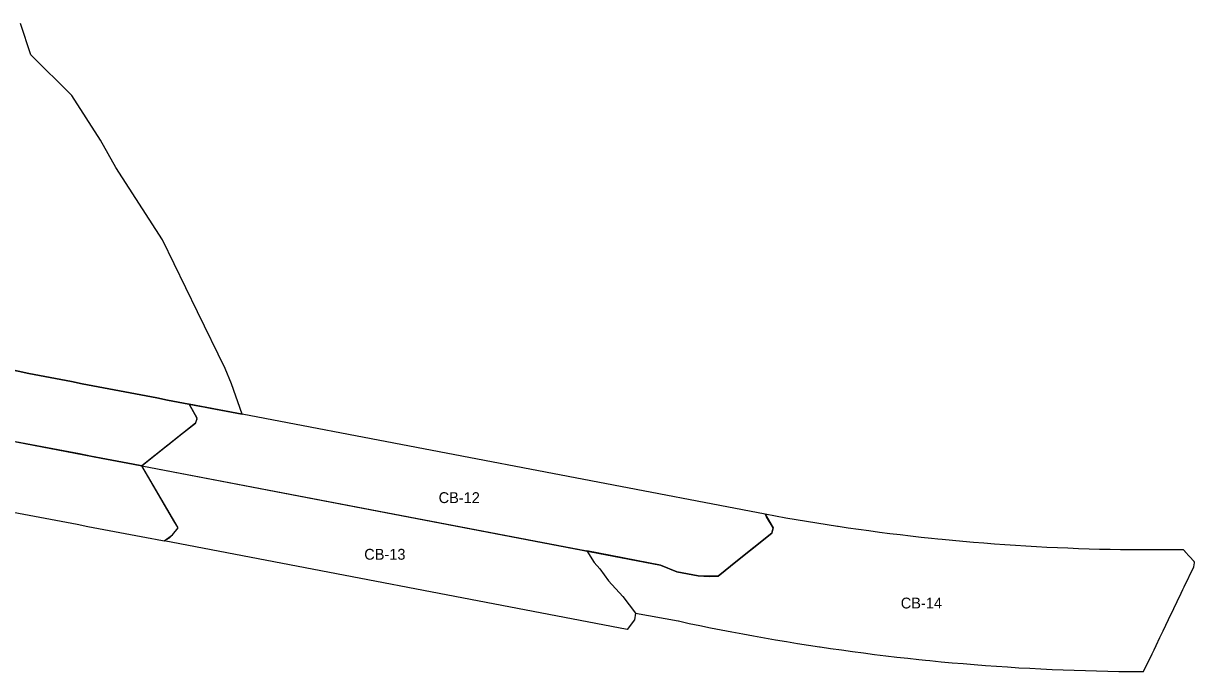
# Model space of a CAD drawing. Extents: x 2451 to 3960, y 2751 to 3762.
# Drawn here: x 3422 to 3960, y 2999 to 3297 of the extents above; entities that cross this region are included whole.
import ezdxf

# ---------------------------------------------------------------- set-up
doc = ezdxf.new("R2010")
doc.units = 0
doc.layers.add('SURVEY - DRAINAGE - Area Shapes', color=7, linetype='Continuous')
doc.layers.add('SURVEY - DRAINAGE - Area Shapes Text', color=7, linetype='Continuous')

msp = doc.modelspace()

# ---------------------------------------------------------------- linework, layer by layer
at = {"layer": 'SURVEY - DRAINAGE - Area Shapes'}
for p, q in [((3501.35, 3115.29), (3501.35, 3115.29)), ((3489.06, 3104.18), (3492.83, 3107.2)), ((3475.92, 3093.68), (3475.92, 3093.68)), ((3490.7, 3068.43), (3490.7, 3068.43)), ((3960.21, 3049.17), (3960.21, 3049.18)), ((3960.21, 3049.16), (3960.21, 3049.17))]:
    msp.add_line(p, q, dxfattribs=at)
for points in [[(3504.34, 3120.85), (3504.34, 3120.82), (3504.34, 3120.82), (3507.42, 3120.31), (3512.32, 3119.36), (3522.13, 3117.42), (3517.23, 3131.44), (3514.23, 3138.52), (3501.62, 3164.62), (3485.54, 3197.81), (3463.94, 3231), (3456.92, 3243.56), (3443.77, 3264.19), (3424.85, 3282.93), (3420.16, 3297.38)], [(3497.58, 3122.12), (3492.67, 3123.06), (3487.76, 3124), (3482.85, 3124.94), (3477.94, 3125.88), (3473.02, 3126.82), (3468.11, 3127.76), (3463.2, 3128.7), (3458.29, 3129.64), (3453.38, 3130.58), (3448.47, 3131.52), (3443.56, 3132.45), (3438.65, 3133.39), (3433.74, 3134.33), (3428.83, 3135.27), (3423.92, 3136.21), (3414.13, 3138.29)], [(3414.13, 3138.29), (3423.92, 3136.21)], [(3423.92, 3136.21), (3428.83, 3135.27), (3433.74, 3134.33), (3438.65, 3133.39), (3443.56, 3132.45), (3448.47, 3131.52), (3453.38, 3130.58), (3458.29, 3129.64), (3463.2, 3128.7), (3468.11, 3127.76), (3473.02, 3126.82), (3477.94, 3125.88), (3482.85, 3124.94), (3487.76, 3124), (3492.67, 3123.06), (3497.58, 3122.12), (3502.49, 3121.18), (3504.34, 3120.82), (3504.34, 3120.84), (3504.34, 3120.84), (3504.34, 3120.85)], [(3501.35, 3115.29), (3501.25, 3115.79), (3501.25, 3115.81), (3499.66, 3118.6), (3498.32, 3120.96), (3498.22, 3121.14), (3497.67, 3122.1), (3497.58, 3122.12)], [(3358.97, 3116.06), (3457.19, 3097.27), (3462.1, 3096.33), (3467.01, 3095.39), (3471.92, 3094.45), (3475.92, 3093.68), (3477.04, 3094.57), (3480.71, 3097.51)], [(3492.83, 3107.2), (3495.07, 3108.98), (3500.58, 3113.4), (3501.35, 3115.28), (3501.35, 3115.29)], [(3475.92, 3093.68), (3471.92, 3094.45), (3467.01, 3095.39), (3462.1, 3096.33), (3457.19, 3097.27), (3452.28, 3098.21), (3447.37, 3099.15), (3442.46, 3100.09), (3437.54, 3101.02), (3432.63, 3101.96), (3427.72, 3102.9), (3422.81, 3103.84), (3417.9, 3104.78)], [(3480.71, 3097.51), (3483.05, 3099.37), (3484.75, 3100.74), (3488.26, 3103.54), (3488.79, 3103.97), (3489.06, 3104.18)], [(3490.7, 3068.43), (3475.92, 3093.68)], [(3416.8, 3072.41), (3421.71, 3071.48)], [(3421.71, 3071.48), (3426.62, 3070.53), (3431.53, 3069.6), (3436.44, 3068.66), (3441.35, 3067.72), (3446.26, 3066.78), (3451.17, 3065.84), (3456.08, 3064.9), (3461, 3063.96), (3465.91, 3063.02), (3470.82, 3062.08), (3475.73, 3061.14), (3480.64, 3060.2)], [(3960.21, 3049.18), (3960.17, 3049.27), (3960.01, 3049.65), (3960, 3049.67), (3957.84, 3052.03), (3955.96, 3054.1), (3955.84, 3054.22), (3955.22, 3054.91), (3955.06, 3055.08), (3950.37, 3055.02), (3945.53, 3054.98), (3940.69, 3054.97), (3935.85, 3054.98), (3931.01, 3055.01), (3926.18, 3055.07), (3921.34, 3055.15), (3916.5, 3055.26), (3911.66, 3055.39), (3906.82, 3055.55), (3901.98, 3055.73), (3897.15, 3055.93), (3892.31, 3056.16), (3887.48, 3056.41), (3882.65, 3056.68), (3877.82, 3056.98), (3872.99, 3057.31), (3868.16, 3057.66), (3863.34, 3058.03), (3858.51, 3058.43), (3853.69, 3058.85), (3848.87, 3059.29), (3844.05, 3059.76), (3842.11, 3059.96), (3839.24, 3060.25), (3834.43, 3060.77), (3829.62, 3061.31), (3824.81, 3061.88), (3820.01, 3062.47), (3815.21, 3063.08), (3810.41, 3063.72), (3805.61, 3064.38), (3800.82, 3065.06), (3796.28, 3065.74), (3796.03, 3065.77), (3791.25, 3066.51), (3786.47, 3067.26), (3781.69, 3068.05), (3776.92, 3068.85), (3772.15, 3069.68), (3767.39, 3070.53), (3762.63, 3071.41), (3766.41, 3065.14), (3765.78, 3062.69), (3749.92, 3050.08), (3741.01, 3042.95), (3731.88, 3042.99), (3722.06, 3044.88), (3714.55, 3048.02), (3680.67, 3054.5)], [(3480.64, 3060.2), (3482.24, 3059.89), (3486.24, 3059.15), (3488.7, 3060.62), (3490.11, 3061.86), (3492.75, 3065.09), (3490.7, 3068.43)], [(3680.67, 3054.5), (3684.09, 3049.26), (3686.7, 3046.33), (3690.58, 3040.72), (3697.17, 3033.49), (3703.11, 3025.89), (3722.72, 3022.29), (3722.83, 3022.27), (3727.69, 3021.07), (3732.6, 3020.13), (3737.51, 3019.19), (3742.42, 3018.25), (3747.33, 3017.31), (3752.35, 3016.36), (3757.39, 3015.43), (3762.43, 3014.53), (3767.47, 3013.65), (3772.52, 3012.8), (3777.57, 3011.98), (3782.63, 3011.17), (3787.69, 3010.4), (3787.95, 3010.36), (3792.75, 3009.65), (3797.82, 3008.92), (3802.89, 3008.22), (3807.97, 3007.55), (3813.05, 3006.9), (3818.13, 3006.28), (3823.22, 3005.68), (3828.3, 3005.11), (3833.39, 3004.56), (3836.43, 3004.25), (3838.49, 3004.04), (3843.58, 3003.54), (3848.68, 3003.07), (3853.78, 3002.63), (3858.89, 3002.21), (3863.99, 3001.81), (3869.1, 3001.44), (3874.21, 3001.1), (3879.32, 3000.78), (3884.43, 3000.49), (3889.54, 3000.23), (3894.65, 2999.98), (3899.77, 2999.77), (3904.89, 2999.58), (3910, 2999.42), (3915.12, 2999.28), (3920.24, 2999.16), (3925.36, 2999.08), (3930.48, 2999.01), (3935.6, 2998.98), (3936.77, 2998.98), (3940.72, 3007.22), (3941.56, 3009), (3942.5, 3010.97), (3944.24, 3014.6), (3945.74, 3017.69), (3948.29, 3023), (3950.66, 3027.96), (3952.21, 3031.24), (3954.04, 3035.07), (3954.83, 3036.72), (3955.48, 3038.06), (3959.84, 3047.16), (3960.18, 3048.98), (3960.21, 3049.16)]]:
    msp.add_lwpolyline(points, dxfattribs=at)
for points in [[(3497.67, 3122.1), (3501.25, 3115.81), (3500.58, 3113.4), (3475.92, 3093.68), (3714.55, 3048.02), (3722.06, 3044.88), (3731.88, 3042.99), (3736.93, 3042.76), (3741.01, 3042.95), (3749.92, 3050.08), (3761.97, 3059.67), (3765.78, 3062.69), (3766.41, 3065.14), (3763.33, 3070.26), (3762.63, 3071.41), (3522.13, 3117.42)], [(3680.67, 3054.5), (3684.09, 3049.26), (3686.7, 3046.33), (3690.58, 3040.72), (3697.17, 3033.49), (3703.11, 3025.89), (3702.57, 3022.82), (3699.28, 3018.36), (3486.24, 3059.15), (3490.11, 3061.86), (3492.75, 3065.09), (3475.92, 3093.68)]]:
    msp.add_lwpolyline(points, close=True, dxfattribs=at)

# ---------------------------------------------------------------- texts
at = {"layer": 'SURVEY - DRAINAGE - Area Shapes Text'}
for s, p in [('CB-12', (3612.5, 3076.55)), ('CB-13', (3578.28, 3050.48)), ('CB-14', (3825.07, 3028.03))]:
    msp.add_text(s, height=5, dxfattribs=at).set_placement(p)

doc.saveas('drawing.dxf')
